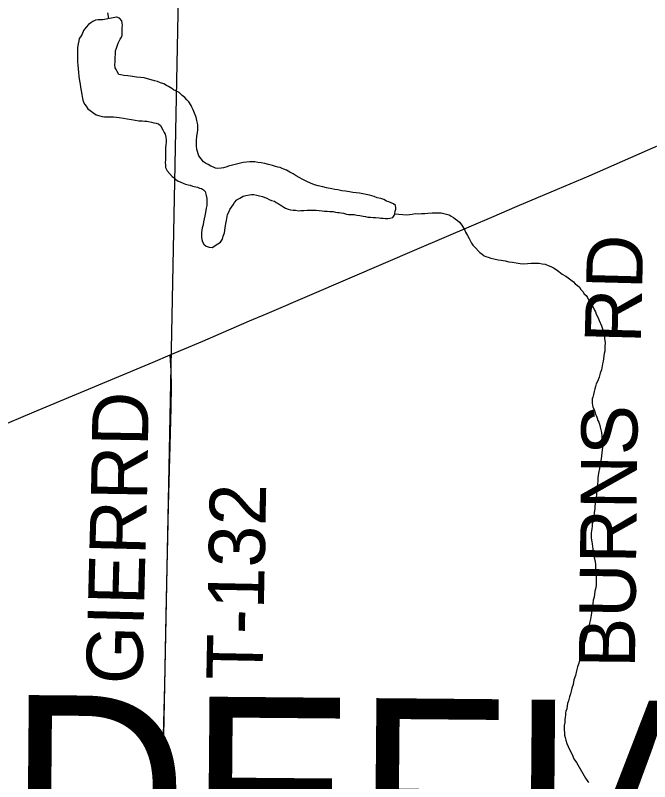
# Model space of a CAD drawing. Extents: x 2.4 to 73.1, y 4.5 to 25.6.
# Drawn here: x 31.4399 to 31.7609, y 21.711 to 22.0988 of the extents above; entities that cross this region are included whole.
import ezdxf

# ---------------------------------------------------------------- set-up
doc = ezdxf.new("R2010")
doc.units = 0
for name, color, linetype in [('GM_X_County_Road', 7, 'Continuous'), ('GM_X_County_Text', 7, 'Continuous'), ('GM_X_Minor_Lake', 7, 'Continuous'), ('GM_X_Minor_River', 7, 'Continuous'), ('GM_X_Section', 7, 'Continuous'), ('GM_X_Township_Road', 7, 'Continuous'), ('GM_X_Township_Road_Text', 7, 'Continuous')]:
    doc.layers.add(name, color=color, linetype=linetype)

msp = doc.modelspace()

# ---------------------------------------------------------------- linework, layer by layer
at = {"layer": 'GM_X_County_Road'}
for points in [[(31.51825, 21.92694), (31.53479, 21.93395), (31.5585, 21.94413), (31.56737, 21.94789), (31.60931, 21.96604), (31.64307, 21.98039), (31.67079, 21.99225), (31.68107, 21.99666), (31.69393, 22.00217), (31.71424, 22.01081), (31.73026, 22.01762), (31.75988, 22.03056), (31.76906, 22.0346)], [(31.01132, 21.71389), (31.03853, 21.72518), (31.06112, 21.7348), (31.07198, 21.73943), (31.09116, 21.74757), (31.11494, 21.75759), (31.14849, 21.77163), (31.1734, 21.78215), (31.18372, 21.78648), (31.19291, 21.79028), (31.20493, 21.79538), (31.22786, 21.805), (31.24193, 21.81085), (31.26142, 21.819), (31.28003, 21.82688), (31.31531, 21.84163), (31.32565, 21.8459), (31.34909, 21.85592), (31.38318, 21.87028), (31.41558, 21.88384), (31.4302, 21.88998), (31.44937, 21.89811), (31.50961, 21.92327), (31.51825, 21.92694)]]:
    msp.add_lwpolyline(points, dxfattribs=at)
at = {"layer": 'GM_X_Minor_Lake'}
for points in [[(31.4911, 22.09792), (31.48424, 22.09651), (31.48271, 22.09653), (31.48176, 22.09655), (31.48043, 22.09638), (31.47909, 22.09564), (31.47813, 22.09508), (31.47697, 22.09415), (31.47581, 22.09284), (31.47445, 22.09115), (31.47366, 22.08926), (31.47288, 22.08795), (31.4723, 22.08701), (31.47209, 22.08587), (31.47168, 22.08436), (31.47146, 22.08246), (31.47144, 22.08075), (31.47141, 22.07885), (31.47138, 22.07695), (31.47135, 22.07524), (31.47151, 22.07353), (31.47168, 22.07181), (31.47184, 22.06991), (31.47199, 22.06782), (31.47234, 22.06572), (31.47269, 22.06401), (31.47286, 22.06249), (31.47321, 22.06058), (31.47356, 22.05867), (31.47391, 22.05677), (31.47427, 22.05524), (31.47501, 22.05371), (31.47575, 22.05275), (31.47668, 22.0514), (31.48082, 22.04849), (31.48271, 22.04789), (31.48385, 22.04768), (31.48499, 22.04747), (31.48632, 22.04745), (31.48746, 22.04743), (31.48841, 22.04742), (31.48955, 22.0474), (31.49107, 22.04719), (31.4924, 22.04716), (31.49468, 22.04675), (31.49657, 22.04634), (31.49866, 22.04611), (31.50055, 22.04571), (31.50245, 22.04549), (31.50416, 22.04546), (31.50549, 22.04525), (31.50644, 22.04523), (31.50739, 22.04503), (31.50891, 22.04481), (31.51004, 22.04441), (31.51118, 22.04421), (31.51232, 22.04381), (31.51344, 22.04303), (31.51455, 22.04092), (31.51529, 22.03958), (31.51566, 22.03863), (31.51601, 22.0371), (31.51618, 22.03577), (31.51617, 22.03463), (31.51615, 22.0333), (31.51593, 22.03178), (31.51591, 22.03045), (31.51589, 22.02931), (31.51587, 22.02798), (31.51585, 22.02684), (31.51584, 22.0257), (31.51582, 22.02437), (31.51598, 22.02304), (31.51596, 22.02171), (31.5167, 22.02018), (31.51932, 22.01729), (31.52026, 22.01651), (31.52119, 22.01574), (31.52232, 22.01496), (31.52327, 22.01456), (31.52516, 22.01377), (31.5261, 22.01338), (31.52743, 22.01298), (31.52838, 22.01277), (31.52951, 22.01237), (31.53046, 22.01217), (31.53216, 22.01176), (31.53311, 22.01137), (31.53406, 22.01116), (31.53519, 22.01057), (31.53593, 22.00961), (31.53647, 22.0077), (31.53683, 22.00618), (31.53681, 22.00504), (31.5368, 22.0039), (31.53677, 22.00257), (31.53656, 22.00124), (31.53615, 21.99897)], [(31.4911, 22.09792), (31.48424, 22.09651), (31.48271, 22.09653), (31.48176, 22.09655), (31.48043, 22.09638), (31.47909, 22.09564), (31.47813, 22.09508), (31.47697, 22.09415), (31.47581, 22.09284), (31.47445, 22.09115), (31.47366, 22.08926), (31.47288, 22.08795), (31.4723, 22.08701), (31.47209, 22.08587), (31.47168, 22.08436), (31.47146, 22.08246), (31.47144, 22.08075), (31.47141, 22.07885), (31.47138, 22.07695), (31.47135, 22.07524), (31.47151, 22.07353), (31.47168, 22.07181), (31.47184, 22.06991), (31.47199, 22.06782), (31.47234, 22.06572), (31.47269, 22.06401), (31.47286, 22.06249), (31.47321, 22.06058), (31.47356, 22.05867), (31.47391, 22.05677), (31.47427, 22.05524), (31.47501, 22.05371), (31.47575, 22.05275), (31.47668, 22.0514), (31.48082, 22.04849), (31.48271, 22.04789), (31.48385, 22.04768), (31.48499, 22.04747), (31.48632, 22.04745), (31.48746, 22.04743), (31.48841, 22.04742), (31.48955, 22.0474), (31.49107, 22.04719), (31.4924, 22.04716), (31.49468, 22.04675), (31.49657, 22.04634), (31.49866, 22.04611), (31.50055, 22.04571), (31.50245, 22.04549), (31.50416, 22.04546), (31.50549, 22.04525), (31.50644, 22.04523), (31.50739, 22.04503), (31.50891, 22.04481), (31.51004, 22.04441), (31.51118, 22.04421), (31.51232, 22.04381), (31.51344, 22.04303), (31.51455, 22.04092), (31.51529, 22.03958), (31.51566, 22.03863), (31.51601, 22.0371), (31.51618, 22.03577), (31.51617, 22.03463), (31.51615, 22.0333), (31.51593, 22.03178), (31.51591, 22.03045), (31.51589, 22.02931), (31.51587, 22.02798), (31.51585, 22.02684), (31.51584, 22.0257), (31.51582, 22.02437), (31.51598, 22.02304), (31.51596, 22.02171), (31.5167, 22.02018), (31.51932, 22.01729), (31.52026, 22.01651), (31.52119, 22.01574), (31.52232, 22.01496), (31.52327, 22.01456), (31.52516, 22.01377), (31.5261, 22.01338), (31.52743, 22.01298), (31.52838, 22.01277), (31.52951, 22.01237), (31.53046, 22.01217), (31.53216, 22.01176), (31.53311, 22.01137), (31.53406, 22.01116), (31.53519, 22.01057), (31.53593, 22.00961), (31.53647, 22.0077), (31.53683, 22.00618), (31.53681, 22.00504), (31.5368, 22.0039), (31.53677, 22.00257), (31.53656, 22.00124), (31.53615, 21.99897)], [(31.49035, 22.07399), (31.49037, 22.07532), (31.4904, 22.07722), (31.49062, 22.0793), (31.49065, 22.08082), (31.49105, 22.08215), (31.49145, 22.08328), (31.49204, 22.08479), (31.49243, 22.08574), (31.49302, 22.08668), (31.49361, 22.08781), (31.494, 22.08875), (31.49402, 22.0897), (31.49404, 22.09103), (31.49406, 22.09255), (31.49408, 22.09388), (31.49391, 22.09483), (31.49374, 22.09598), (31.49262, 22.09732), (31.4913, 22.09791), (31.4911, 22.09792)], [(31.49035, 22.07399), (31.49037, 22.07532), (31.4904, 22.07722), (31.49062, 22.0793), (31.49065, 22.08082), (31.49105, 22.08215), (31.49145, 22.08328), (31.49204, 22.08479), (31.49243, 22.08574), (31.49302, 22.08668), (31.49361, 22.08781), (31.494, 22.08875), (31.49402, 22.0897), (31.49404, 22.09103), (31.49406, 22.09255), (31.49408, 22.09388), (31.49391, 22.09483), (31.49374, 22.09598), (31.49262, 22.09732), (31.4913, 22.09791), (31.4911, 22.09792)], [(31.62772, 22.00474), (31.6264, 22.00552), (31.62489, 22.00611), (31.62299, 22.00652), (31.62148, 22.00711), (31.6192, 22.00772), (31.6175, 22.00813), (31.61579, 22.00853), (31.61408, 22.00875), (31.61238, 22.00897), (31.61067, 22.00919), (31.60896, 22.0094), (31.60707, 22.00981), (31.60517, 22.01003), (31.60308, 22.01045), (31.60156, 22.01066), (31.60005, 22.01106), (31.59739, 22.01149), (31.5955, 22.01209), (31.59322, 22.0125), (31.59133, 22.0131), (31.58925, 22.0139), (31.58736, 22.01469), (31.58548, 22.01567), (31.58359, 22.01665), (31.58208, 22.01762), (31.58058, 22.01859), (31.57888, 22.01938), (31.57718, 22.02036), (31.57586, 22.02095), (31.57492, 22.02134), (31.57397, 22.02174), (31.57283, 22.02195), (31.57151, 22.02235), (31.56999, 22.02275), (31.5681, 22.02335), (31.56621, 22.02376), (31.56431, 22.02417), (31.5626, 22.02439), (31.56108, 22.0246), (31.55861, 22.02464), (31.5569, 22.02448), (31.55518, 22.02432), (31.55385, 22.02396), (31.54907, 22.02289), (31.54774, 22.02254), (31.5464, 22.02199), (31.54525, 22.02163), (31.54411, 22.02145), (31.54239, 22.02129), (31.54125, 22.0215), (31.54012, 22.0219), (31.5388, 22.02249), (31.53748, 22.02327), (31.53616, 22.02405), (31.53522, 22.02463), (31.53391, 22.02617), (31.53279, 22.02771), (31.53243, 22.02867), (31.53207, 22.02981), (31.5317, 22.03096), (31.53154, 22.03286), (31.53158, 22.03533), (31.53181, 22.03761), (31.53203, 22.03951), (31.53224, 22.04083), (31.53226, 22.04197), (31.53228, 22.0433), (31.5321, 22.04425), (31.53174, 22.04559), (31.53139, 22.04731), (31.53066, 22.04922), (31.52993, 22.05094), (31.52919, 22.05228), (31.52882, 22.05324), (31.52771, 22.05497), (31.52677, 22.05612), (31.52565, 22.05728), (31.52433, 22.05825), (31.52284, 22.05979), (31.52114, 22.06058), (31.52001, 22.06117), (31.51907, 22.06175), (31.51737, 22.06273), (31.51643, 22.06331), (31.51511, 22.06409), (31.51341, 22.06469), (31.51189, 22.06529), (31.51038, 22.06569), (31.50507, 22.0671), (31.50318, 22.06732), (31.50128, 22.06754), (31.49919, 22.06777), (31.49691, 22.06818), (31.49483, 22.06841), (31.49331, 22.06862), (31.49236, 22.06883), (31.49143, 22.07036), (31.49088, 22.07132), (31.49051, 22.07228), (31.49035, 22.07399)], [(31.62772, 22.00474), (31.6264, 22.00552), (31.62489, 22.00611), (31.62299, 22.00652), (31.62148, 22.00711), (31.6192, 22.00772), (31.6175, 22.00813), (31.61579, 22.00853), (31.61408, 22.00875), (31.61238, 22.00897), (31.61067, 22.00919), (31.60896, 22.0094), (31.60707, 22.00981), (31.60517, 22.01003), (31.60308, 22.01045), (31.60156, 22.01066), (31.60005, 22.01106), (31.59739, 22.01149), (31.5955, 22.01209), (31.59322, 22.0125), (31.59133, 22.0131), (31.58925, 22.0139), (31.58736, 22.01469), (31.58548, 22.01567), (31.58359, 22.01665), (31.58208, 22.01762), (31.58058, 22.01859), (31.57888, 22.01938), (31.57718, 22.02036), (31.57586, 22.02095), (31.57492, 22.02134), (31.57397, 22.02174), (31.57283, 22.02195), (31.57151, 22.02235), (31.56999, 22.02275), (31.5681, 22.02335), (31.56621, 22.02376), (31.56431, 22.02417), (31.5626, 22.02439), (31.56108, 22.0246), (31.55861, 22.02464), (31.5569, 22.02448), (31.55518, 22.02432), (31.55385, 22.02396), (31.54907, 22.02289), (31.54774, 22.02254), (31.5464, 22.02199), (31.54525, 22.02163), (31.54411, 22.02145), (31.54239, 22.02129), (31.54125, 22.0215), (31.54012, 22.0219), (31.5388, 22.02249), (31.53748, 22.02327), (31.53616, 22.02405), (31.53522, 22.02463), (31.53391, 22.02617), (31.53279, 22.02771), (31.53243, 22.02867), (31.53207, 22.02981), (31.5317, 22.03096), (31.53154, 22.03286), (31.53158, 22.03533), (31.53181, 22.03761), (31.53203, 22.03951), (31.53224, 22.04083), (31.53226, 22.04197), (31.53228, 22.0433), (31.5321, 22.04425), (31.53174, 22.04559), (31.53139, 22.04731), (31.53066, 22.04922), (31.52993, 22.05094), (31.52919, 22.05228), (31.52882, 22.05324), (31.52771, 22.05497), (31.52677, 22.05612), (31.52565, 22.05728), (31.52433, 22.05825), (31.52284, 22.05979), (31.52114, 22.06058), (31.52001, 22.06117), (31.51907, 22.06175), (31.51737, 22.06273), (31.51643, 22.06331), (31.51511, 22.06409), (31.51341, 22.06469), (31.51189, 22.06529), (31.51038, 22.06569), (31.50507, 22.0671), (31.50318, 22.06732), (31.50128, 22.06754), (31.49919, 22.06777), (31.49691, 22.06818), (31.49483, 22.06841), (31.49331, 22.06862), (31.49236, 22.06883), (31.49143, 22.07036), (31.49088, 22.07132), (31.49051, 22.07228), (31.49035, 22.07399)], [(31.53615, 21.99897), (31.53574, 21.99726), (31.53553, 21.99575), (31.53512, 21.99423), (31.53491, 21.99272), (31.5345, 21.9912), (31.5343, 21.99007), (31.53409, 21.98893), (31.53407, 21.98779), (31.53405, 21.98646), (31.53422, 21.98532), (31.53458, 21.98417), (31.53533, 21.98302), (31.53645, 21.98205), (31.53796, 21.98146), (31.53948, 21.98124), (31.54236, 21.9831), (31.54371, 21.98403), (31.54468, 21.98553), (31.54509, 21.98705), (31.54569, 21.98875), (31.5461, 21.99121), (31.54652, 21.99348), (31.54673, 21.995), (31.54694, 21.99595), (31.54735, 21.99803), (31.54794, 21.99916), (31.54853, 22.00048), (31.54931, 22.0018), (31.55009, 22.00293), (31.55087, 22.00406), (31.55203, 22.00537), (31.55357, 22.00629), (31.55529, 22.00721), (31.55663, 22.00757), (31.55835, 22.00793), (31.55949, 22.0081), (31.56063, 22.00808), (31.56215, 22.00787), (31.56348, 22.00746), (31.56499, 22.00706), (31.56613, 22.00666), (31.56726, 22.00626), (31.56839, 22.00568), (31.56953, 22.00509), (31.57104, 22.00468), (31.57198, 22.0041), (31.57292, 22.00351), (31.57387, 22.00293), (31.57481, 22.00234), (31.57575, 22.00176), (31.57669, 22.00117), (31.57802, 22.00077), (31.57915, 22.00038), (31.58048, 22.00016), (31.58162, 22.00015), (31.58314, 21.99993), (31.58447, 22.0001), (31.58599, 22.00008), (31.58752, 22.00024), (31.59208, 22.00017), (31.5936, 21.99996), (31.59512, 21.99993), (31.59645, 21.99972), (31.59778, 21.9997), (31.59911, 21.99949), (31.60082, 21.99946), (31.60196, 21.99925), (31.6029, 21.99905), (31.60385, 21.99903), (31.6048, 21.99883), (31.60594, 21.99862), (31.60745, 21.99822), (31.60859, 21.99801), (31.60992, 21.99799), (31.61144, 21.99796), (31.61277, 21.99775), (31.61429, 21.99754), (31.616, 21.99713), (31.61713, 21.99692), (31.61827, 21.99672), (31.6196, 21.99669), (31.62093, 21.99648), (31.62226, 21.99646), (31.62397, 21.99624), (31.62492, 21.99623), (31.62606, 21.99621), (31.6272, 21.996), (31.62834, 21.99599), (31.62948, 21.99616), (31.63101, 21.99651), (31.6316, 21.99745), (31.63199, 21.9984), (31.6322, 21.99972), (31.63241, 22.00067), (31.63242, 22.00162), (31.63225, 22.00257), (31.63131, 22.00335), (31.63018, 22.00394), (31.62885, 22.00434), (31.62772, 22.00474)], [(31.53615, 21.99897), (31.53574, 21.99726), (31.53553, 21.99575), (31.53512, 21.99423), (31.53491, 21.99272), (31.5345, 21.9912), (31.5343, 21.99007), (31.53409, 21.98893), (31.53407, 21.98779), (31.53405, 21.98646), (31.53422, 21.98532), (31.53458, 21.98417), (31.53533, 21.98302), (31.53645, 21.98205), (31.53796, 21.98146), (31.53948, 21.98124), (31.54236, 21.9831), (31.54371, 21.98403), (31.54468, 21.98553), (31.54509, 21.98705), (31.54569, 21.98875), (31.5461, 21.99121), (31.54652, 21.99348), (31.54673, 21.995), (31.54694, 21.99595), (31.54735, 21.99803), (31.54794, 21.99916), (31.54853, 22.00048), (31.54931, 22.0018), (31.55009, 22.00293), (31.55087, 22.00406), (31.55203, 22.00537), (31.55357, 22.00629), (31.55529, 22.00721), (31.55663, 22.00757), (31.55835, 22.00793), (31.55949, 22.0081), (31.56063, 22.00808), (31.56215, 22.00787), (31.56348, 22.00746), (31.56499, 22.00706), (31.56613, 22.00666), (31.56726, 22.00626), (31.56839, 22.00568), (31.56953, 22.00509), (31.57104, 22.00468), (31.57198, 22.0041), (31.57292, 22.00351), (31.57387, 22.00293), (31.57481, 22.00234), (31.57575, 22.00176), (31.57669, 22.00117), (31.57802, 22.00077), (31.57915, 22.00038), (31.58048, 22.00016), (31.58162, 22.00015), (31.58314, 21.99993), (31.58447, 22.0001), (31.58599, 22.00008), (31.58752, 22.00024), (31.59208, 22.00017), (31.5936, 21.99996), (31.59512, 21.99993), (31.59645, 21.99972), (31.59778, 21.9997), (31.59911, 21.99949), (31.60082, 21.99946), (31.60196, 21.99925), (31.6029, 21.99905), (31.60385, 21.99903), (31.6048, 21.99883), (31.60594, 21.99862), (31.60745, 21.99822), (31.60859, 21.99801), (31.60992, 21.99799), (31.61144, 21.99796), (31.61277, 21.99775), (31.61429, 21.99754), (31.616, 21.99713), (31.61713, 21.99692), (31.61827, 21.99672), (31.6196, 21.99669), (31.62093, 21.99648), (31.62226, 21.99646), (31.62397, 21.99624), (31.62492, 21.99623), (31.62606, 21.99621), (31.6272, 21.996), (31.62834, 21.99599), (31.62948, 21.99616), (31.63101, 21.99651), (31.6316, 21.99745), (31.63199, 21.9984), (31.6322, 21.99972), (31.63241, 22.00067), (31.63242, 22.00162), (31.63225, 22.00257), (31.63131, 22.00335), (31.63018, 22.00394), (31.62885, 22.00434), (31.62772, 22.00474)]]:
    msp.add_lwpolyline(points, dxfattribs=at)
at = {"layer": 'GM_X_Minor_River'}
for points in [[(31.48657, 22.10008), (31.48715, 22.09712)], [(31.63199, 21.9984), (31.63807, 21.99792), (31.6394, 21.99809), (31.64074, 21.99826), (31.64226, 21.99843), (31.64378, 21.9984), (31.6455, 21.99856), (31.64721, 21.99854), (31.64873, 21.9987), (31.65083, 21.99886), (31.65235, 21.99883), (31.65368, 21.99881), (31.65539, 21.99879), (31.65672, 21.99857), (31.65804, 21.99817), (31.65937, 21.99777), (31.6605, 21.99718), (31.66163, 21.99641), (31.66257, 21.99582), (31.6637, 21.99504), (31.66463, 21.99408), (31.66594, 21.99254), (31.66742, 21.99005), (31.66779, 21.98909), (31.66871, 21.98736), (31.66964, 21.98583), (31.67001, 21.98487), (31.67075, 21.98353), (31.67149, 21.98257), (31.67224, 21.98161), (31.67504, 21.97871), (31.67617, 21.97794), (31.67711, 21.97716), (31.67806, 21.97677), (31.67919, 21.97637), (31.68052, 21.97597), (31.68203, 21.97556), (31.68431, 21.97515), (31.68583, 21.97493), (31.68772, 21.97452), (31.68962, 21.97411), (31.69151, 21.97389), (31.69341, 21.97348), (31.69531, 21.97326), (31.69721, 21.97304), (31.69911, 21.9732), (31.70101, 21.97336), (31.70292, 21.97333), (31.70501, 21.9733), (31.70653, 21.97308), (31.70804, 21.97287), (31.70956, 21.97228), (31.71088, 21.97168), (31.7122, 21.97109), (31.71352, 21.97012), (31.71502, 21.96915), (31.71671, 21.96779), (31.71841, 21.96682), (31.71973, 21.96604), (31.72104, 21.96487), (31.72236, 21.9639), (31.72329, 21.96294), (31.72442, 21.96216), (31.72536, 21.9612), (31.7261, 21.96004), (31.72704, 21.95908), (31.72778, 21.95793), (31.72871, 21.95696), (31.72946, 21.956), (31.73001, 21.95485), (31.73132, 21.95293), (31.73187, 21.95197), (31.73242, 21.95082), (31.73297, 21.94967), (31.73353, 21.94872), (31.73389, 21.94757), (31.73444, 21.94642), (31.735, 21.94527), (31.73536, 21.94432), (31.73646, 21.94164), (31.73701, 21.94011), (31.73737, 21.93915), (31.73773, 21.93782), (31.73809, 21.9361), (31.73807, 21.93515), (31.73825, 21.9342), (31.73842, 21.93306), (31.7382, 21.93116), (31.73818, 21.93002), (31.73816, 21.92888), (31.73796, 21.92774), (31.73775, 21.92642), (31.73753, 21.9249), (31.73732, 21.92376), (31.73711, 21.92244), (31.73691, 21.92149), (31.73649, 21.91941), (31.7359, 21.91771)], [(31.7359, 21.91771), (31.73529, 21.91563), (31.7345, 21.91355), (31.73391, 21.91223), (31.73351, 21.9109), (31.73311, 21.90977), (31.7329, 21.90844), (31.73249, 21.90693), (31.73209, 21.90561), (31.73189, 21.90466), (31.73187, 21.90371), (31.73185, 21.90257), (31.7322, 21.90047), (31.73276, 21.89932), (31.73312, 21.89818), (31.73348, 21.89703), (31.73403, 21.89588), (31.7344, 21.89493), (31.73476, 21.89378), (31.73513, 21.89283), (31.73549, 21.89187), (31.73585, 21.89035), (31.73621, 21.88901), (31.73657, 21.88767), (31.73673, 21.88596), (31.73702, 21.88026), (31.73678, 21.87741), (31.73636, 21.87438), (31.73594, 21.87172), (31.73552, 21.86945), (31.7351, 21.86718), (31.73468, 21.86471), (31.73466, 21.86319), (31.73444, 21.86149), (31.73423, 21.85978), (31.73401, 21.85826), (31.73398, 21.85655), (31.73377, 21.85485), (31.73355, 21.85333), (31.73334, 21.85181), (31.73313, 21.8503), (31.73311, 21.84916), (31.73289, 21.84707), (31.73267, 21.84536), (31.73246, 21.84404), (31.73225, 21.84271), (31.73185, 21.84139), (31.73183, 21.84025), (31.73162, 21.83892), (31.73141, 21.83797), (31.73139, 21.83683), (31.73137, 21.83532), (31.73135, 21.83436), (31.73153, 21.83322), (31.7317, 21.83227), (31.73188, 21.83132), (31.73205, 21.82998), (31.73222, 21.82865), (31.73239, 21.82732), (31.73274, 21.82598), (31.73291, 21.82427), (31.73326, 21.82256), (31.73342, 21.82046), (31.73358, 21.81837), (31.73392, 21.81608), (31.73389, 21.81437), (31.73386, 21.81248), (31.73383, 21.81057), (31.73362, 21.80906), (31.73321, 21.80735), (31.733, 21.80584), (31.73278, 21.80432), (31.73238, 21.80281), (31.73216, 21.8011), (31.73131, 21.79522), (31.7309, 21.79314), (31.73049, 21.79125), (31.73008, 21.78954), (31.72967, 21.78784), (31.72927, 21.78614), (31.72886, 21.78424), (31.72826, 21.78235), (31.72766, 21.78046), (31.72725, 21.77857), (31.72665, 21.77706), (31.72624, 21.77516), (31.72564, 21.77327), (31.72503, 21.771), (31.72443, 21.76911), (31.72383, 21.76703), (31.72342, 21.76476), (31.72262, 21.76249), (31.7222, 21.76022), (31.7216, 21.75833), (31.7212, 21.75681), (31.7208, 21.75549), (31.72039, 21.75398), (31.71979, 21.7519), (31.71939, 21.75057), (31.71918, 21.74943), (31.71897, 21.74792)], [(31.71897, 21.74792), (31.71857, 21.74659), (31.71836, 21.74565), (31.71835, 21.7447), (31.71814, 21.74356), (31.71793, 21.74242), (31.71791, 21.74091), (31.71769, 21.73939), (31.71768, 21.73844), (31.71766, 21.7373), (31.71782, 21.73559), (31.7178, 21.73445), (31.71817, 21.7333), (31.71853, 21.73197), (31.71907, 21.73025), (31.71962, 21.72872), (31.72072, 21.72661), (31.72165, 21.7247), (31.72256, 21.72259), (31.72387, 21.72067), (31.72701, 21.71511), (31.7285, 21.71281), (31.72998, 21.7105)]]:
    msp.add_lwpolyline(points, dxfattribs=at)
at = {"layer": 'GM_X_Section'}
msp.add_lwpolyline([(31.52296, 22.13382), (32.02184, 22.12942), (32.01678, 21.62643), (32.00315, 21.62654), (31.51301, 21.63229)], close=True, dxfattribs=at)
at = {"layer": 'GM_X_Township_Road'}
msp.add_lwpolyline([(31.51267, 21.63144), (31.51286, 21.64287), (31.51344, 21.67396), (31.51376, 21.69044), (31.51439, 21.71655), (31.51492, 21.73458), (31.51553, 21.75976), (31.51617, 21.79521), (31.51669, 21.81945), (31.51704, 21.83407), (31.51741, 21.85054), (31.51821, 21.881), (31.51877, 21.90028), (31.51888, 21.91085), (31.51877, 21.91924), (31.51863, 21.92141), (31.51825, 21.92694)], dxfattribs=at)

# ---------------------------------------------------------------- texts
at = {"layer": 'GM_X_County_Text'}
msp.add_text('DEFIANCE COUNTY', height=0.094697, rotation=359.4936, dxfattribs=at).set_placement((31.43551, 21.6602))
at = {"layer": 'GM_X_Township_Road_Text'}
for s, rotation, p in [('RD', 88.531, (31.75639, 21.93257)), ('RD', 89.028, (31.50656, 21.85319)), ('BURNS', 89.3821, (31.75346, 21.76848)), ('T-132', 88.8765, (31.56495, 21.76222)), ('GIER', 88.5392, (31.50406, 21.76003))]:
    msp.add_text(s, height=0.028409, rotation=rotation, dxfattribs=at).set_placement(p)

doc.saveas('drawing.dxf')
